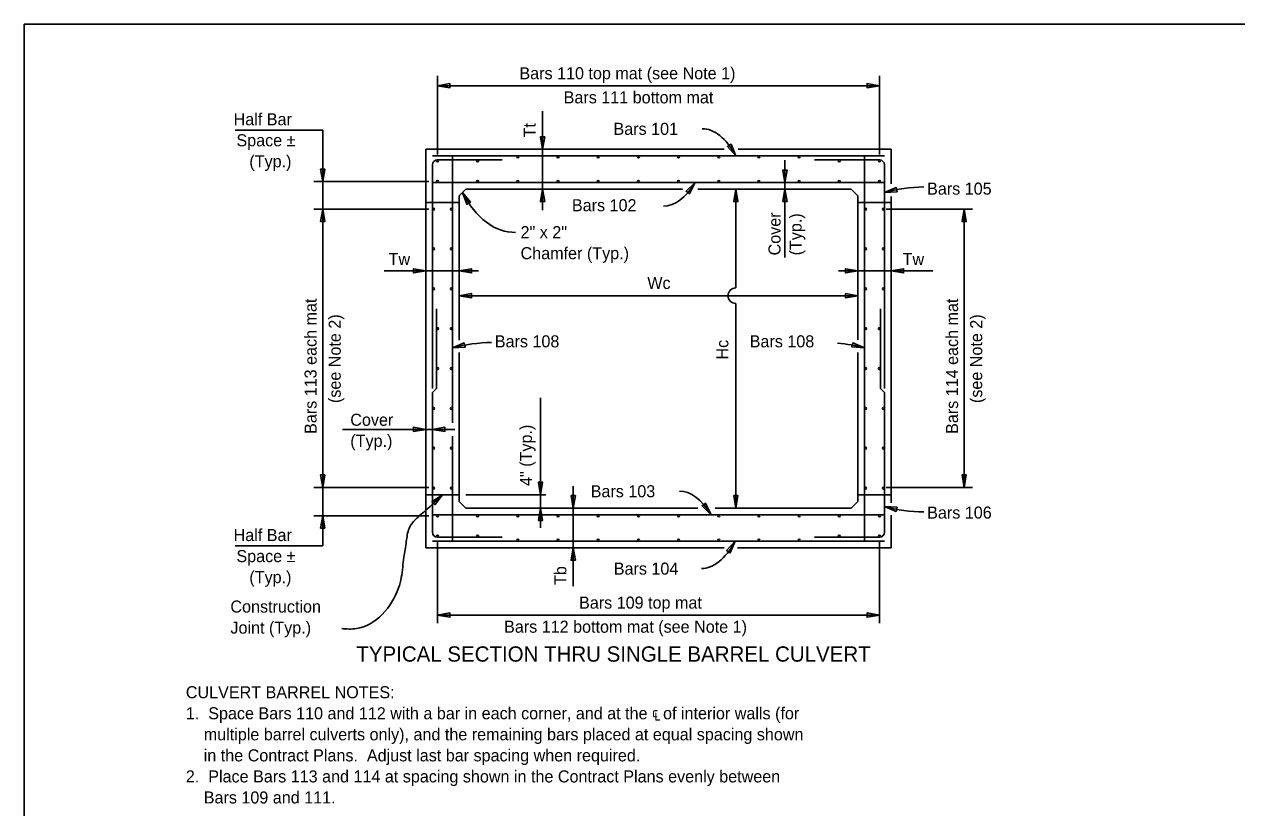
# Model space of a CAD drawing. Extents: x -178 to 179, y -5 to 45.
# Drawn here: x 2.47 to 32.88, y 23.18 to 42.84 of the extents above; entities that cross this region are included whole.
import ezdxf

# ---------------------------------------------------------------- set-up
doc = ezdxf.new("R2010")
doc.units = 0
for name, color, linetype in [('AdhocPoint_dp', 7, 'Continuous'), ('Leader', 7, 'Continuous'), ('PlotBorder_dp', 7, 'Continuous'), ('Rebar', 7, 'Continuous'), ('StrMiscConc', 7, 'Continuous'), ('StrMiscConc_h', 7, 'Continuous')]:
    doc.layers.add(name, color=color, linetype=linetype)

msp = doc.modelspace()

# ---------------------------------------------------------------- linework, layer by layer
at = {"layer": 'Leader'}
msp.add_arc((20.317, 36.028), 0.195, 90, 270, dxfattribs=at)
for centre, major_axis, ratio, start_param, end_param in [((19.55, 36.458), (0.076, -3.758), 0.38143, 2.52174, 3.141593), ((14.741, 40.431), (-0.051, 2.815), 0.604093, 2.259611, 3.141593), ((18.58, 42.036), (-0.076, -3.758), 0.38143, 0, 0.575555), ((18.979, 27.366), (-0.076, 3.758), 0.38143, 5.70763, 6.283185), ((19.531, 32.944), (0.076, 3.758), 0.38143, 3.141593, 3.761445)]:
    msp.add_ellipse(centre, major_axis=major_axis, ratio=ratio, start_param=start_param, end_param=end_param, dxfattribs=at)
msp.add_spline([(10.435, 27.675), (10.802, 27.675), (11.86, 28.695), (11.965, 29.218), (11.992, 29.466), (12.055, 29.86), (12.124, 30.189), (12.32, 30.449), (12.548, 30.65), (12.961, 31.034)], degree=3, dxfattribs=at)
at = {"layer": 'PlotBorder_dp'}
for p, q in [((12.836, 39.567), (12.836, 41.548)), ((23.919, 39.567), (23.919, 41.548)), ((12.836, 41.297), (23.919, 41.297)), ((15.471, 40.659), (15.471, 39.701)), ((7.764, 40.181), (9.958, 40.181)), ((9.958, 38.893), (9.958, 40.181)), ((15.471, 38.701), (15.471, 39.701)), ((21.549, 38.868), (21.549, 39.43)), ((12.62, 38.893), (9.738, 38.893)), ((9.958, 38.201), (9.958, 38.893)), ((15.471, 38.701), (15.471, 38.17)), ((20.317, 38.701), (20.317, 36.223)), ((21.549, 38.701), (21.549, 38.868)), ((21.549, 36.986), (21.549, 38.701)), ((12.62, 38.201), (9.738, 38.201)), ((9.958, 38.201), (9.958, 31.219)), ((24.089, 38.201), (26.251, 38.201)), ((26.043, 38.201), (26.043, 31.219)), ((11.499, 36.653), (12.544, 36.653)), ((13.377, 36.653), (12.544, 36.653)), ((13.377, 36.653), (13.861, 36.653)), ((23.377, 36.653), (22.894, 36.653)), ((24.211, 36.653), (23.377, 36.653)), ((25.256, 36.653), (24.211, 36.653)), ((13.377, 36.028), (23.377, 36.028)), ((20.317, 35.833), (20.317, 30.701)), ((15.42, 33.468), (15.42, 31.034)), ((10.456, 32.675), (12.544, 32.675)), ((12.544, 32.675), (12.711, 32.675)), ((12.711, 32.675), (13.273, 32.675)), ((12.62, 31.219), (9.738, 31.219)), ((9.958, 30.509), (9.958, 31.219)), ((13.547, 31.034), (15.552, 31.034)), ((15.42, 31.034), (15.42, 30.701)), ((16.24, 30.701), (16.24, 31.251)), ((24.089, 31.219), (26.251, 31.219)), ((12.62, 30.509), (9.738, 30.509)), ((9.958, 29.749), (9.958, 30.509)), ((15.42, 30.701), (15.42, 30.207)), ((16.24, 29.701), (16.24, 30.701)), ((12.836, 29.856), (12.836, 27.811)), ((23.919, 29.856), (23.919, 27.811)), ((7.764, 29.749), (9.958, 29.749)), ((16.24, 28.743), (16.24, 29.701)), ((12.836, 28.016), (23.919, 28.016))]:
    msp.add_line(p, q, dxfattribs=at)
for points in [[(2.474, 42.838), (63.281, 42.838), (63.281, 3.352), (2.474, 3.352)], [(12.836, 41.297), (13.148, 41.244), (13.148, 41.35)], [(23.919, 41.297), (23.607, 41.35), (23.607, 41.244)], [(15.471, 39.701), (15.524, 40.013), (15.418, 40.013)], [(20.321, 39.534), (20.197, 39.826), (20.108, 39.769)], [(9.958, 38.893), (10.011, 39.205), (9.905, 39.205)], [(21.549, 38.868), (21.496, 39.18), (21.602, 39.18)], [(13.461, 38.618), (13.576, 38.323), (13.667, 38.377)], [(15.471, 38.701), (15.418, 38.389), (15.524, 38.389)], [(19.297, 38.868), (19.068, 38.649), (19.152, 38.586)], [(20.317, 38.701), (20.265, 38.389), (20.37, 38.389)], [(21.549, 38.701), (21.602, 38.389), (21.496, 38.389)], [(24.044, 38.621), (24.361, 38.636), (24.338, 38.739)], [(9.958, 38.201), (9.905, 37.889), (10.011, 37.889)], [(26.043, 38.201), (25.99, 37.889), (26.096, 37.889)], [(12.544, 36.653), (12.232, 36.705), (12.232, 36.6)], [(13.377, 36.653), (13.69, 36.6), (13.69, 36.705)], [(23.377, 36.653), (23.065, 36.6), (23.065, 36.705)], [(24.211, 36.653), (24.523, 36.705), (24.523, 36.6)], [(13.377, 36.028), (13.69, 35.975), (13.69, 36.081)], [(23.377, 36.028), (23.065, 36.081), (23.065, 35.975)], [(13.211, 34.721), (13.527, 34.739), (13.503, 34.842)], [(23.544, 34.721), (23.253, 34.845), (23.228, 34.742)], [(12.544, 32.675), (12.232, 32.727), (12.232, 32.622)], [(12.711, 32.675), (13.023, 32.622), (13.023, 32.727)], [(9.958, 31.219), (10.011, 31.532), (9.905, 31.532)], [(15.42, 31.034), (15.473, 31.347), (15.367, 31.347)], [(26.043, 31.219), (26.096, 31.532), (25.99, 31.532)], [(12.961, 31.034), (12.696, 30.86), (12.768, 30.783)], [(16.24, 30.701), (16.187, 31.013), (16.293, 31.013)], [(20.317, 30.701), (20.37, 31.013), (20.265, 31.013)], [(19.696, 30.534), (19.556, 30.819), (19.47, 30.757)], [(24.044, 30.737), (24.338, 30.618), (24.361, 30.721)], [(9.958, 30.509), (9.905, 30.197), (10.011, 30.197)], [(15.42, 30.701), (15.367, 30.389), (15.473, 30.389)], [(20.302, 29.868), (20.175, 29.577), (20.087, 29.635)], [(16.24, 29.701), (16.293, 29.389), (16.187, 29.389)], [(12.836, 28.016), (13.148, 27.963), (13.148, 28.069)], [(23.919, 28.016), (23.607, 28.069), (23.607, 27.963)]]:
    msp.add_lwpolyline(points, close=True, dxfattribs=at)
for centre, start, end in [((25.119, 34.418), 91.2114, 104.3468), ((14.286, 30.518), 91.2114, 104.3468), ((22.469, 30.518), 75.6532, 84.7223), ((25.119, 34.94), 255.6532, 268.7886)]:
    msp.add_arc(centre, 4.339, start, end, dxfattribs=at)
at = {"layer": 'Rebar'}
for p, q in [((12.711, 39.534), (24.044, 39.534)), ((13.211, 39.534), (13.211, 32.84)), ((23.544, 39.534), (23.544, 29.868)), ((12.711, 33.701), (12.711, 39.309)), ((12.836, 39.434), (14.461, 39.434)), ((23.919, 39.434), (22.294, 39.434)), ((24.044, 33.701), (24.044, 39.309)), ((12.711, 38.868), (24.044, 38.868)), ((12.811, 35.701), (12.811, 33.701)), ((23.944, 35.701), (23.944, 33.701)), ((12.811, 33.701), (12.711, 33.601)), ((12.711, 33.601), (12.711, 30.093)), ((23.944, 33.701), (24.044, 33.601)), ((24.044, 33.601), (24.044, 30.093)), ((13.211, 32.504), (13.211, 29.868)), ((12.711, 30.534), (24.044, 30.534)), ((12.711, 29.868), (24.044, 29.868)), ((12.836, 29.968), (14.461, 29.968)), ((23.919, 29.968), (22.294, 29.968))]:
    msp.add_line(p, q, dxfattribs=at)
for centre in [(14.851, 39.509), (15.859, 39.509), (16.866, 39.509), (17.874, 39.509), (18.881, 39.509), (19.889, 39.509), (20.896, 39.509), (21.904, 39.509), (12.836, 39.409), (13.843, 39.409), (22.912, 39.409), (23.919, 39.409), (12.836, 38.893), (13.843, 38.893), (14.851, 38.893), (15.859, 38.893), (16.866, 38.893), (17.874, 38.893), (18.881, 38.893), (19.889, 38.893), (20.896, 38.893), (21.904, 38.893), (22.912, 38.893), (23.919, 38.893), (12.736, 38.201), (13.186, 38.201), (23.569, 38.201), (24.019, 38.201), (12.736, 37.201), (13.186, 37.201), (23.569, 37.201), (24.019, 37.201), (12.736, 36.201), (13.186, 36.201), (23.569, 36.201), (24.019, 36.201), (12.836, 35.201), (13.186, 35.201), (23.569, 35.201), (23.919, 35.201), (12.836, 34.201), (13.186, 34.201), (23.569, 34.201), (23.919, 34.201), (12.736, 33.201), (13.186, 33.201), (23.569, 33.201), (24.019, 33.201), (12.736, 32.201), (13.186, 32.201), (23.569, 32.201), (24.019, 32.201), (12.736, 31.201), (13.186, 31.201), (23.569, 31.201), (24.019, 31.201), (12.836, 30.509), (13.843, 30.509), (14.851, 30.509), (15.859, 30.509), (16.866, 30.509), (17.874, 30.509), (18.881, 30.509), (19.889, 30.509), (20.896, 30.509), (21.904, 30.509), (22.912, 30.509), (23.919, 30.509), (12.836, 29.993), (13.843, 29.993), (14.851, 29.893), (15.859, 29.893), (16.866, 29.893), (17.874, 29.893), (18.881, 29.893), (19.889, 29.893), (20.896, 29.893), (21.904, 29.893), (22.912, 29.993), (23.919, 29.993)]:
    msp.add_circle(centre, 0.025, dxfattribs=at)
for centre, start, end in [((12.836, 39.309), 90, 180), ((23.919, 39.309), 0, 90), ((12.836, 30.093), 180, 270), ((23.919, 30.093), 270, 0)]:
    msp.add_arc(centre, 0.125, start, end, dxfattribs=at)
at = {"layer": 'StrMiscConc'}
for p, q in [((12.544, 39.701), (12.544, 29.701)), ((12.544, 39.701), (20.023, 39.701)), ((20.377, 39.701), (24.211, 39.701)), ((24.211, 39.701), (24.211, 38.834)), ((13.377, 38.534), (13.544, 38.701)), ((13.544, 38.701), (18.977, 38.701)), ((19.364, 38.701), (23.211, 38.701)), ((23.211, 38.701), (23.377, 38.534)), ((13.377, 34.912), (13.377, 38.534)), ((23.377, 38.534), (23.377, 34.919)), ((24.211, 38.516), (24.211, 30.829)), ((13.377, 30.868), (13.377, 34.606)), ((23.377, 34.607), (23.377, 30.868)), ((13.544, 30.701), (13.377, 30.868)), ((23.377, 30.868), (23.211, 30.701)), ((19.362, 30.701), (13.544, 30.701)), ((23.211, 30.701), (19.798, 30.701)), ((24.211, 30.525), (24.211, 29.701)), ((20.022, 29.701), (12.544, 29.701)), ((24.211, 29.701), (20.363, 29.701))]:
    msp.add_line(p, q, dxfattribs=at)
at = {"layer": 'StrMiscConc_h'}
for p, q in [((13.377, 38.368), (12.544, 38.368)), ((23.377, 38.368), (24.211, 38.368)), ((13.377, 31.034), (12.544, 31.034)), ((23.377, 31.034), (24.211, 31.034))]:
    msp.add_line(p, q, dxfattribs=at)

# ---------------------------------------------------------------- texts
at = {"layer": 'AdhocPoint_dp'}
for s, height, p in [('Bars 110 top mat (see Note 1)', 0.3024, (14.891, 41.458)), ('Bars 111 bottom mat', 0.3024, (16, 40.853)), ('Half Bar', 0.3024, (7.724, 40.304)), ('Bars 101', 0.3024, (17.249, 40.063)), ('Space ±', 0.3024, (7.795, 39.776)), ('(Typ.)', 0.3024, (8.119, 39.248)), ('Bars 105', 0.3024, (25.113, 38.563)), ('Bars 102', 0.3024, (16.208, 38.147)), ('2" x 2"', 0.3024, (14.92, 37.471)), ('Tw', 0.3024, (11.611, 36.795)), ('Chamfer (Typ.)', 0.3024, (14.92, 36.943)), ('Tw', 0.3024, (24.5, 36.795)), ('Wc', 0.3024, (18.097, 36.197)), ('Bars 108', 0.3024, (14.274, 34.732)), ('Bars 108', 0.3024, (20.665, 34.732)), ('Cover', 0.3024, (10.65, 32.764)), ('(Typ.)', 0.3024, (10.65, 32.236)), ('Bars 103', 0.3024, (16.678, 30.971)), ('Bars 106', 0.3024, (25.115, 30.436)), ('Half Bar', 0.3024, (7.724, 29.872)), ('Space ±', 0.3024, (7.795, 29.344)), ('Bars 104', 0.3024, (17.257, 29.03)), ('(Typ.)', 0.3024, (8.119, 28.816)), ('Construction', 0.3024, (7.644, 28.078)), ('Joint (Typ.)', 0.3024, (7.644, 27.55)), ('TYPICAL SECTION THRU SINGLE BARREL CULVERT', 0.384, (10.801, 26.847)), ('CULVERT BARREL NOTES:', 0.3024, (6.526, 25.929)), ('1.  Space Bars 110 and 112 with a bar in each corner, and at the ℄ of interior walls (for', 0.3024, (6.526, 25.401)), ('    multiple barrel culverts only), and the remaining bars placed at equal spacing shown', 0.3024, (6.526, 24.873)), ('    in the Contract Plans.  Adjust last bar spacing when required.', 0.3024, (6.526, 24.345)), ('2.  Place Bars 113 and 114 at spacing shown in the Contract Plans evenly between', 0.3024, (6.526, 23.817)), ('    Bars 109 and 111.', 0.3024, (6.526, 23.289))]:
    msp.add_text(s, height=height, dxfattribs=at).set_placement(p)
for s, rotation, p in [('Tt', 90, (15.299, 39.999)), ('Cover', 90, (21.439, 37.039)), ('(Typ.)', 90, (21.967, 37.039)), ('Bars 113 each mat', 90, (9.805, 32.561)), ('Bars 114 each mat', 90, (25.89, 32.561)), ('(see Note 2)', 90, (10.41, 33.335)), ('(see Note 2)', 90, (26.495, 33.335)), ('Hc', 90, (20.13, 34.427)), ('4" (Typ.)', 90, (15.205, 31.255)), ('Tb', 90, (16.068, 28.771)), ('Bars 109 top mat', 360, (16.386, 28.177)), ('Bars 112 bottom mat (see Note 1)', 360, (14.506, 27.573))]:
    msp.add_text(s, height=0.3024, rotation=rotation, dxfattribs=at).set_placement(p)

doc.saveas('drawing.dxf')
